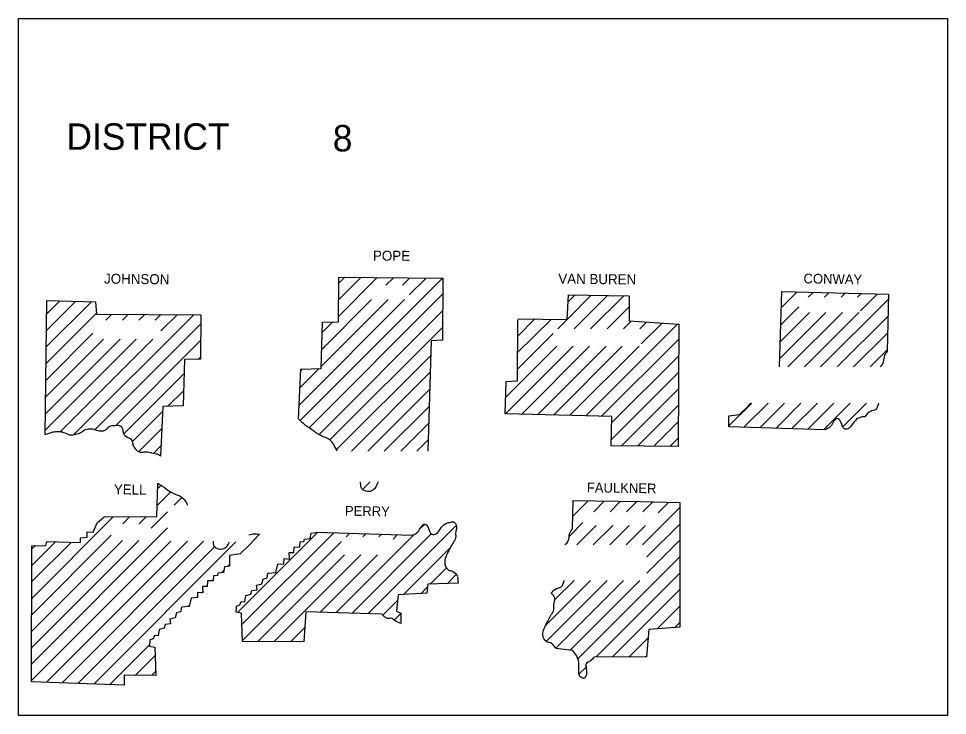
# Model space of a CAD drawing. Extents: x 76 to 6945, y -3933 to 2152.
# Drawn here: x 6539.5 to 6939.5, y -3253.4 to -2953.4 of the extents above; entities that cross this region are included whole.
import ezdxf

# ---------------------------------------------------------------- set-up
doc = ezdxf.new("R2010")
doc.units = 0
doc.layers.add('R_Draft', color=7, linetype='Continuous')

msp = doc.modelspace()

# ---------------------------------------------------------------- linework, layer by layer
at = {"layer": 'R_Draft'}
msp.add_lwpolyline([(6539.46, -3253.36), (6539.46, -2953.36), (6939.46, -2953.36), (6939.46, -3253.36)], close=True, dxfattribs=at)
for points in [[(6659.96, -3125.66), (6660.96, -3104.26), (6669.76, -3103.96), (6670.36, -3084.06), (6677.26, -3083.96), (6677.36, -3064.76)], [(6660.76, -3126.36), (6722.06, -3065.06), (6722.06, -3064.96)], [(6677.26, -3081.56), (6693.86, -3064.86)], [(6677.26, -3074.46), (6686.86, -3064.86)], [(6677.26, -3067.36), (6679.86, -3064.86)], [(6677.36, -3064.76), (6722.16, -3065.06)], [(6697.66, -3068.16), (6700.86, -3064.96)], [(6704.76, -3068.16), (6707.96, -3064.96)], [(6707.86, -3072.16), (6714.96, -3065.06)], [(6722.16, -3065.06), (6721.96, -3091.76), (6717.16, -3092.16), (6715.66, -3139.66)], [(6867.16, -3103.36), (6868.16, -3070.86)], [(6867.86, -3077.96), (6874.76, -3071.06)], [(6868.16, -3070.86), (6914.06, -3071.96), (6913.46, -3096.66)], [(6879.56, -3073.36), (6881.66, -3071.26)], [(6886.56, -3073.36), (6888.56, -3071.36)], [(6893.66, -3073.36), (6895.56, -3071.46)], [(6900.76, -3073.36), (6902.36, -3071.76)], [(6902.06, -3079.16), (6909.36, -3071.86)], [(6550.86, -3132.56), (6551.56, -3074.76)], [(6551.26, -3094.86), (6570.86, -3075.26)], [(6551.36, -3087.76), (6564.06, -3075.06)], [(6551.46, -3080.56), (6557.06, -3074.96)], [(6551.56, -3074.76), (6572.56, -3075.26), (6573.06, -3080.56)], [(6660.26, -3119.76), (6705.66, -3074.36)], [(6664.66, -3129.56), (6722.06, -3072.06)], [(6669.86, -3103.06), (6698.56, -3074.36)], [(6670.06, -3095.76), (6691.46, -3074.36)], [(6754.46, -3082.66), (6775.76, -3082.86), (6776.26, -3072.36), (6802.06, -3072.66)], [(6771.66, -3086.96), (6775.76, -3082.86), (6786.06, -3072.46)], [(6776.06, -3075.46), (6779.06, -3072.46)], [(6778.76, -3086.96), (6793.06, -3072.56)], [(6785.76, -3086.96), (6800.06, -3072.66)], [(6802.36, -3072.66), (6802.46, -3083.56), (6823.86, -3084.96), (6823.56, -3137.66)], [(6884.86, -3103.36), (6913.96, -3074.26)], [(6668.86, -3132.36), (6722.06, -3079.16)], [(6792.86, -3086.96), (6802.36, -3077.46)], [(6867.26, -3099.76), (6887.16, -3079.86)], [(6867.46, -3092.46), (6880.06, -3079.86)], [(6867.66, -3085.26), (6875.46, -3077.46)], [(6870.76, -3103.36), (6894.26, -3079.86)], [(6877.86, -3103.36), (6901.36, -3079.86)], [(6551.26, -3102.06), (6572.96, -3080.26)], [(6563.06, -3132.56), (6614.86, -3080.86)], [(6573.06, -3080.56), (6617.96, -3080.86)], [(6577.06, -3083.26), (6579.66, -3080.66)], [(6584.16, -3083.26), (6586.76, -3080.66)], [(6591.26, -3083.26), (6593.76, -3080.76)], [(6598.26, -3083.26), (6600.76, -3080.76)], [(6617.96, -3080.86), (6617.86, -3100.06), (6610.96, -3100.16), (6610.36, -3120.06), (6601.56, -3120.36), (6600.56, -3141.76)], [(6600.76, -3087.86), (6607.76, -3080.86)], [(6670.16, -3088.56), (6674.76, -3083.96)], [(6749.06, -3123.56), (6749.46, -3109.66), (6754.26, -3109.26), (6754.46, -3083.26)], [(6754.36, -3097.16), (6768.76, -3082.86)], [(6754.46, -3090.06), (6761.76, -3082.66)], [(6754.46, -3082.96), (6754.76, -3082.66)], [(6799.96, -3086.96), (6803.26, -3083.66)], [(6891.96, -3103.36), (6913.76, -3081.56)], [(6572.36, -3130.36), (6617.86, -3084.86)], [(6673.56, -3134.66), (6721.96, -3086.36)], [(6783.76, -3124.36), (6823.16, -3084.96)], [(6806.96, -3086.96), (6809.86, -3084.06)], [(6807.56, -3093.46), (6816.56, -3084.56)], [(6550.96, -3130.56), (6590.16, -3091.36)], [(6551.06, -3123.46), (6583.16, -3091.36)], [(6551.06, -3116.36), (6576.06, -3091.36)], [(6551.16, -3109.16), (6571.46, -3088.86)], [(6557.26, -3131.36), (6597.26, -3091.36)], [(6581.16, -3128.66), (6617.86, -3091.96)], [(6754.36, -3104.26), (6769.66, -3088.96)], [(6790.66, -3124.46), (6823.76, -3091.36)], [(6899.06, -3103.36), (6913.66, -3088.76)], [(6749.16, -3123.66), (6749.16, -3123.56), (6778.26, -3094.46)], [(6749.36, -3116.36), (6771.26, -3094.46)], [(6756.16, -3123.66), (6785.36, -3094.46)], [(6763.06, -3123.86), (6792.46, -3094.46)], [(6769.96, -3123.96), (6799.46, -3094.46)], [(6776.86, -3124.16), (6806.66, -3094.46)], [(6906.16, -3103.36), (6913.46, -3095.96)], [(6616.76, -3100.16), (6617.86, -3099.06)], [(6676.26, -3139.06), (6716.96, -3098.46)], [(6794.96, -3127.26), (6823.76, -3098.56)], [(6660.56, -3112.36), (6668.96, -3103.96)], [(6584.86, -3132.06), (6610.76, -3106.16)], [(6660.96, -3104.96), (6661.76, -3104.16)], [(6682.76, -3139.66), (6716.76, -3105.66)], [(6794.76, -3134.56), (6823.76, -3105.56)], [(6603.66, -3120.36), (6610.56, -3113.46)], [(6689.86, -3139.66), (6716.46, -3113.06)], [(6799.16, -3137.26), (6823.66, -3112.76)], [(6806.06, -3137.46), (6823.66, -3119.76)], [(6845.36, -3129.06), (6845.36, -3124.46), (6849.86, -3123.76), (6853.76, -3120.06), (6854.86, -3118.96)], [(6845.36, -3128.66), (6855.16, -3118.96)], [(6851.96, -3129.16), (6862.26, -3118.96)], [(6858.76, -3129.46), (6869.26, -3118.96)], [(6865.66, -3129.66), (6876.36, -3118.96)], [(6872.46, -3129.86), (6883.46, -3118.96)], [(6879.36, -3130.16), (6890.56, -3118.96)], [(6886.16, -3130.36), (6897.56, -3118.96)], [(6894.46, -3129.16), (6904.66, -3118.96)], [(6588.66, -3135.36), (6601.36, -3122.66)], [(6696.96, -3139.66), (6716.26, -3120.36)], [(6794.66, -3137.26), (6794.96, -3124.66), (6749.26, -3123.56)], [(6704.06, -3139.66), (6716.06, -3127.66)], [(6813.06, -3137.46), (6823.56, -3126.96)], [(6591.26, -3139.76), (6601.16, -3129.86)], [(6886.66, -3130.36), (6845.46, -3129.06)], [(6710.96, -3139.66), (6715.76, -3134.86)], [(6819.86, -3137.66), (6823.56, -3134.06)], [(6597.56, -3140.56), (6600.76, -3137.36)], [(6823.56, -3137.66), (6794.46, -3137.26)], [(6544.96, -3238.86), (6545.16, -3180.36), (6551.16, -3180.16), (6551.66, -3178.56), (6566.16, -3178.96), (6566.06, -3176.86), (6568.96, -3176.56), (6569.06, -3174.26), (6571.56, -3174.46), (6573.26, -3170.46), (6576.26, -3167.86), (6599.06, -3167.76), (6599.46, -3153.36)], [(6599.46, -3155.66), (6600.76, -3154.36)], [(6687.56, -3156.06), (6690.86, -3152.86)], [(6599.16, -3163.06), (6605.06, -3157.16)], [(6606.46, -3162.86), (6609.76, -3159.56)], [(6778.06, -3172.96), (6778.36, -3160.86)], [(6778.16, -3160.86), (6807.26, -3161.26)], [(6778.16, -3167.56), (6784.66, -3161.06)], [(6787.16, -3165.66), (6791.66, -3161.06)], [(6807.26, -3161.26), (6824.26, -3161.76), (6824.26, -3215.36), (6810.86, -3216.36), (6809.86, -3228.16), (6787.36, -3228.26)], [(6794.16, -3165.66), (6798.66, -3161.16)], [(6801.26, -3165.66), (6805.66, -3161.26)], [(6808.16, -3179.96), (6824.26, -3163.86)], [(6808.36, -3165.66), (6812.56, -3161.46)], [(6814.86, -3166.16), (6819.36, -3161.66)], [(6545.16, -3202.96), (6580.16, -3167.86)], [(6584.36, -3170.86), (6587.26, -3167.86)], [(6591.36, -3170.86), (6594.36, -3167.86)], [(6596.56, -3172.76), (6603.66, -3165.66)], [(6689.86, -3209.56), (6727.96, -3171.56)], [(6712.26, -3173.06), (6714.36, -3170.96)], [(6776.66, -3176.16), (6782.46, -3170.26)], [(6779.86, -3179.96), (6788.26, -3171.56)], [(6786.96, -3179.96), (6795.36, -3171.56)], [(6794.06, -3179.96), (6802.46, -3171.56)], [(6801.06, -3179.96), (6809.46, -3171.56)], [(6810.06, -3185.16), (6824.26, -3170.96)], [(6545.06, -3231.26), (6603.66, -3172.66)], [(6545.16, -3210.06), (6579.36, -3175.76)], [(6643.16, -3175.36), (6638.76, -3180.06), (6634.86, -3183.76), (6630.36, -3184.46), (6630.36, -3189.16), (6628.16, -3189.46), (6627.76, -3191.86), (6625.26, -3192.06), (6625.06, -3193.16), (6623.36, -3193.26), (6623.26, -3195.36), (6620.86, -3195.46), (6620.66, -3197.86), (6618.66, -3197.86), (6618.76, -3200.66), (6616.56, -3200.46), (6616.46, -3202.66), (6613.76, -3202.86), (6612.96, -3206.46), (6609.56, -3206.76), (6609.26, -3208.76), (6607.46, -3209.26), (6606.96, -3211.36), (6604.66, -3211.86), (6604.86, -3213.96), (6602.56, -3214.16), (6602.16, -3215.76), (6600.06, -3216.36), (6599.56, -3219.06), (6597.96, -3218.96), (6597.46, -3220.36), (6595.96, -3220.86), (6595.86, -3223.56), (6598.16, -3223.96), (6598.56, -3236.16)], [(6635.86, -3221.56), (6635.46, -3209.36), (6633.16, -3208.96), (6633.26, -3206.26), (6634.76, -3205.76), (6635.26, -3204.36), (6636.86, -3204.46), (6637.36, -3201.76), (6639.46, -3201.16), (6639.86, -3199.56), (6642.16, -3199.36), (6641.96, -3197.26), (6644.26, -3196.76), (6644.76, -3194.66), (6646.56, -3194.16), (6646.86, -3192.16), (6650.26, -3191.86), (6651.06, -3188.26), (6653.76, -3188.06), (6653.86, -3185.86), (6656.06, -3186.06), (6655.96, -3183.26), (6657.96, -3183.26), (6658.16, -3180.86), (6660.56, -3180.76), (6660.66, -3178.66), (6662.36, -3178.56), (6662.56, -3177.46), (6665.06, -3177.26), (6665.46, -3174.86), (6667.66, -3174.56), (6667.66, -3174.46)], [(6633.76, -3209.06), (6668.36, -3174.46)], [(6635.66, -3214.26), (6675.26, -3174.76)], [(6667.76, -3174.46), (6708.96, -3175.76)], [(6676.26, -3209.06), (6709.66, -3175.66)], [(6680.56, -3176.46), (6682.06, -3174.96)], [(6683.06, -3209.36), (6717.16, -3175.26)], [(6687.66, -3176.46), (6688.96, -3175.16)], [(6694.66, -3176.46), (6695.76, -3175.36)], [(6700.76, -3177.46), (6702.56, -3175.66)], [(6545.06, -3224.26), (6591.26, -3178.06)], [(6545.06, -3238.36), (6605.06, -3178.36)], [(6545.16, -3217.06), (6584.16, -3178.06)], [(6545.16, -3188.76), (6555.36, -3178.66)], [(6545.16, -3195.76), (6562.16, -3178.86)], [(6551.46, -3239.06), (6612.16, -3178.36)], [(6558.16, -3239.36), (6619.16, -3178.36)], [(6571.86, -3239.86), (6633.06, -3178.66)], [(6635.86, -3221.16), (6678.46, -3178.56)], [(6810.06, -3192.16), (6824.26, -3177.96)], [(6545.16, -3181.66), (6546.56, -3180.36)], [(6564.96, -3239.66), (6623.86, -3180.76)], [(6705.16, -3201.36), (6725.46, -3181.06)], [(6642.46, -3221.56), (6679.86, -3184.26)], [(6649.56, -3221.56), (6686.86, -3184.26)], [(6669.36, -3208.86), (6693.96, -3184.26)], [(6780.26, -3229.06), (6824.26, -3185.06)], [(6626.76, -3191.96), (6627.96, -3190.86)], [(6629.46, -3189.26), (6630.36, -3188.46), (6630.56, -3188.26)], [(6716.76, -3196.86), (6723.66, -3189.96)], [(6728.46, -3193.66), (6728.76, -3196.36), (6715.66, -3196.86), (6715.26, -3200.76), (6702.96, -3201.46), (6702.26, -3208.46), (6704.06, -3209.36), (6704.06, -3213.86)], [(6724.06, -3196.66), (6727.96, -3192.76)], [(6766.36, -3214.66), (6785.76, -3195.26)], [(6766.76, -3221.36), (6792.86, -3195.26)], [(6770.56, -3203.36), (6778.76, -3195.26)], [(6770.76, -3224.46), (6799.96, -3195.26)], [(6777.16, -3225.16), (6807.06, -3195.26)], [(6788.26, -3228.16), (6824.26, -3192.16)], [(6712.66, -3200.96), (6715.46, -3198.16)], [(6795.26, -3228.16), (6824.26, -3199.16)], [(6616.06, -3202.76), (6616.36, -3202.36)], [(6618.06, -3200.66), (6618.76, -3200.06)], [(6696.26, -3210.26), (6702.76, -3203.76)], [(6612.26, -3206.56), (6613.16, -3205.66)], [(6814.46, -3216.06), (6824.26, -3206.26)], [(6695.86, -3209.76), (6663.16, -3208.76), (6662.26, -3221.66), (6635.86, -3221.56)], [(6701.26, -3212.36), (6704.06, -3209.46)], [(6656.66, -3221.56), (6662.76, -3215.56)], [(6822.06, -3215.56), (6824.26, -3213.36)], [(6802.36, -3228.16), (6810.56, -3219.96)], [(6578.66, -3240.16), (6595.96, -3222.86)], [(6589.76, -3236.06), (6598.26, -3227.56)], [(6777.96, -3225.36), (6770.76, -3224.56)], [(6809.46, -3228.16), (6809.96, -3227.66)], [(6596.86, -3236.06), (6598.56, -3234.36)], [(6780.96, -3235.36), (6783.86, -3232.56)], [(6584.86, -3240.36), (6544.96, -3238.86)], [(6598.56, -3236.16), (6584.96, -3236.06), (6584.86, -3240.36)]]:
    msp.add_lwpolyline(points, dxfattribs=at)
for points in [[(6913.46, -3096.66), (6912.16, -3098.96), (6911.56, -3101.96), (6910.46, -3103.36)], [(6909.86, -3118.96), (6909.76, -3119.26), (6908.46, -3121.76), (6906.46, -3122.46), (6903.96, -3124.76)], [(6663.06, -3128.56), (6661.16, -3126.76), (6659.96, -3125.66)], [(6903.96, -3124.76), (6902.76, -3124.86), (6901.16, -3125.36), (6899.66, -3126.56), (6898.46, -3128.16), (6896.56, -3129.96), (6895.06, -3129.96), (6893.66, -3127.36), (6892.06, -3125.56), (6890.46, -3126.86), (6889.16, -3128.96), (6886.66, -3130.36)], [(6600.56, -3141.76), (6599.76, -3141.16), (6597.56, -3140.66), (6594.16, -3139.96), (6591.96, -3140.16), (6590.66, -3139.56), (6589.76, -3138.56), (6588.86, -3137.06), (6588.36, -3134.96), (6586.66, -3133.86), (6584.76, -3132.16), (6584.46, -3130.36), (6582.96, -3128.66), (6580.86, -3128.66), (6578.46, -3129.06), (6577.06, -3130.36), (6574.66, -3131.06), (6572.46, -3130.46), (6570.36, -3130.06), (6568.16, -3130.46), (6566.16, -3131.76), (6564.16, -3132.46), (6561.46, -3132.66), (6558.96, -3131.66), (6556.56, -3131.26), (6554.16, -3131.46), (6550.86, -3132.56)], [(6676.66, -3139.66), (6675.16, -3136.76), (6673.26, -3134.56), (6669.86, -3133.06), (6666.56, -3130.96), (6663.06, -3128.56)], [(6599.46, -3153.36), (6602.96, -3155.76), (6606.26, -3157.86), (6609.66, -3159.36), (6611.56, -3161.56), (6612.26, -3162.86)], [(6694.26, -3152.86), (6693.26, -3154.96), (6691.96, -3156.46), (6689.66, -3156.96), (6687.26, -3155.76), (6686.76, -3153.26), (6686.66, -3152.86)], [(6708.96, -3175.76), (6711.46, -3174.36), (6712.76, -3172.26), (6714.36, -3170.96), (6715.96, -3172.76), (6717.36, -3175.36), (6718.86, -3175.36), (6720.76, -3173.56), (6721.96, -3171.96), (6723.46, -3170.76), (6725.06, -3170.26), (6726.76, -3170.06), (6728.06, -3171.96), (6727.66, -3174.96), (6727.66, -3176.96), (6726.56, -3179.06), (6725.36, -3181.26), (6724.06, -3183.76), (6723.06, -3186.46), (6723.26, -3189.06), (6724.66, -3190.76), (6726.26, -3191.26), (6728.46, -3193.46)], [(6638.66, -3175.66), (6641.06, -3175.16), (6643.16, -3175.36)], [(6774.76, -3179.96), (6776.16, -3178.26), (6776.76, -3175.26), (6778.06, -3172.96)], [(6623.26, -3178.36), (6623.66, -3180.56), (6626.06, -3181.76), (6628.36, -3181.26), (6629.66, -3179.76), (6630.26, -3178.66)], [(6768.86, -3200.76), (6771.06, -3198.76), (6773.06, -3198.06), (6774.36, -3195.56), (6774.46, -3195.26)], [(6770.76, -3224.36), (6768.56, -3222.16), (6766.96, -3221.66), (6765.56, -3219.96), (6765.36, -3217.36), (6766.36, -3214.66), (6767.66, -3212.16), (6768.86, -3209.96), (6769.96, -3207.86), (6769.96, -3205.86), (6770.36, -3202.86), (6768.86, -3200.76)], [(6704.06, -3213.86), (6701.46, -3212.46), (6699.96, -3211.56), (6698.36, -3211.66), (6697.06, -3210.86), (6695.86, -3209.76)], [(6787.36, -3228.26), (6785.56, -3229.96), (6783.86, -3231.16), (6783.86, -3232.56), (6784.06, -3234.96), (6783.06, -3237.36), (6781.46, -3236.76), (6780.66, -3233.96), (6780.66, -3230.56), (6779.66, -3227.56), (6777.96, -3225.36)]]:
    msp.add_spline(points, degree=3, dxfattribs=at)

# ---------------------------------------------------------------- texts
for s, p in [('DISTRICT', (6560.06, -3009.86)), ('8', (6674.76, -3010.56))]:
    msp.add_text(s, height=11.4, dxfattribs=at).set_placement(p)
for s, height, rotation, p in [('POPE', 4.301, 359.6155, (6692.06, -3057.56)), ('JOHNSON', 4.301, 359.3514, (6576.26, -3067.46)), ('VAN BUREN', 4.301, 359.3508, (6771.86, -3067.46)), ('CONWAY', 4.199, 359.0371, (6877.46, -3067.36)), ('YELL', 4.301, 359.1987, (6580.46, -3158.16)), ('FAULKNER', 4.201, 359.2486, (6784.16, -3157.36)), ('PERRY', 4.201, 359.0858, (6679.96, -3167.36))]:
    msp.add_text(s, height=height, rotation=rotation, dxfattribs=at).set_placement(p)

doc.saveas('drawing.dxf')
